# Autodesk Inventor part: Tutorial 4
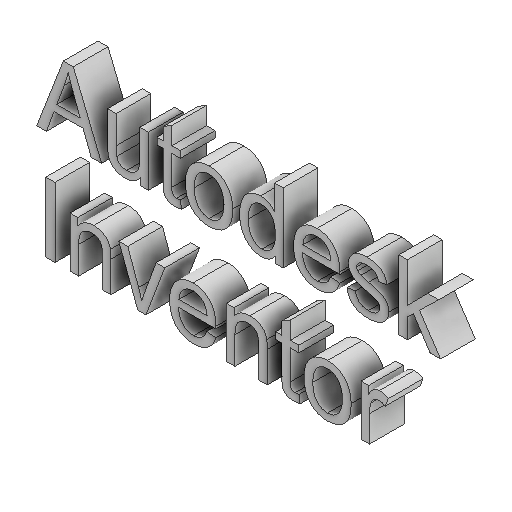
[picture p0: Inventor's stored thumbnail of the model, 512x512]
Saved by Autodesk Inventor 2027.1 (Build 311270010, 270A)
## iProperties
Created: 2021-04
Part Number: Tutorial 4
Material: Generic
Document SubType Name: Modeling
Designer: ASUS Laptop
Density: 1 g/cm^3
Appearance: Default
Author: ASUS Laptop
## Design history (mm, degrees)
sketch "Sketch1"
  geometry: L1 (4.899, 17.404)-(34.549, 17.404); L2 (34.549, 17.404)-(34.549, 2.449); L3 (34.549, 2.449)-(4.899, 2.449); L4 (4.899, 2.449)-(4.899, 17.404); 1 further point
  constraints: 2 other
extrude "Extrusion1" new body sketch "Sketch1" distance "d0" = 2.5; taper "d1" = 0 deg
body "Solid1"
